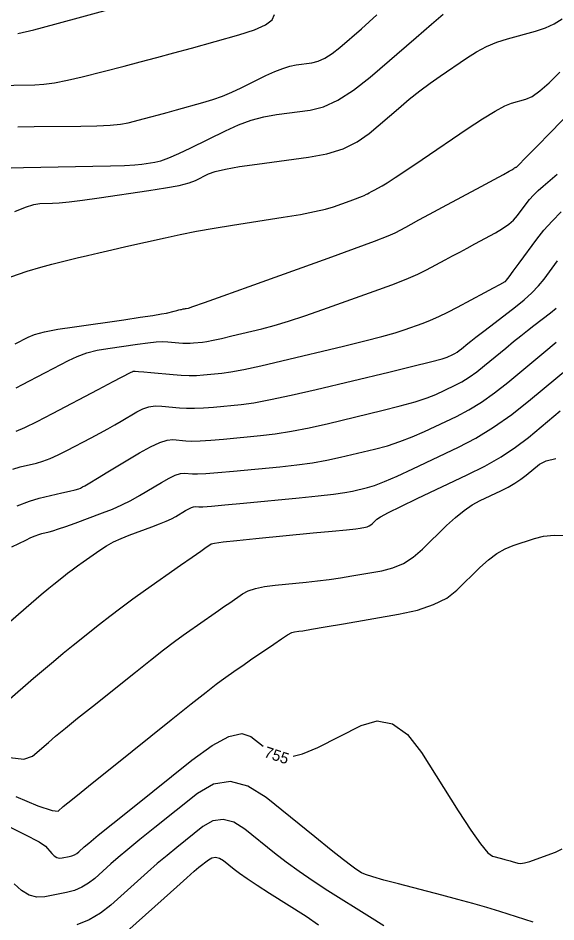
# Model space of a CAD drawing. Extents: x 2082232 to 2083549, y 592624 to 593832.
# Drawn here: x 2082518.1 to 2082552.2, y 592892.1 to 592949.4 of the extents above; entities that cross this region are included whole.
import ezdxf

# ---------------------------------------------------------------- set-up
doc = ezdxf.new("R2010")
doc.units = 0
doc.layers.add('DT_X_Contour_Major', color=7, linetype='Continuous')
doc.layers.add('DT_X_Contour_Minor', color=7, linetype='Continuous')

msp = doc.modelspace()

# ---------------------------------------------------------------- linework, layer by layer
at = {"layer": 'DT_X_Contour_Major'}
for points in [[(2082515.408, 592944.858), (2082515.81, 592944.932), (2082516.581, 592945.049), (2082517.244, 592945.12), (2082517.801, 592945.146), (2082519.143, 592945.157), (2082519.708, 592945.192), (2082520.398, 592945.29), (2082521.212, 592945.45), (2082522.149, 592945.673), (2082524.816, 592946.35), (2082525.832, 592946.611), (2082526.881, 592946.888), (2082527.963, 592947.179), (2082529.077, 592947.485), (2082532.093, 592948.32), (2082533.082, 592948.637), (2082533.788, 592948.96), (2082534.209, 592949.29), (2082534.347, 592949.627)], [(2082517.894, 592928.73), (2082518.717, 592929.161), (2082519.132, 592929.323), (2082519.763, 592929.486), (2082520.609, 592929.651), (2082521.669, 592929.817), (2082524.782, 592930.262), (2082525.827, 592930.414), (2082526.627, 592930.535), (2082527.182, 592930.626), (2082527.492, 592930.686), (2082527.991, 592930.807), (2082528.16, 592930.847), (2082528.292, 592930.879), (2082528.388, 592930.902), (2082528.448, 592930.916), (2082528.558, 592930.941), (2082528.601, 592930.95), (2082528.646, 592930.959), (2082528.695, 592930.968), (2082528.747, 592930.976), (2082528.888, 592930.998), (2082529.17, 592931.09), (2082529.908, 592931.348), (2082531.102, 592931.772), (2082532.752, 592932.364), (2082537.762, 592934.162), (2082539.437, 592934.769), (2082540.705, 592935.241), (2082541.566, 592935.578), (2082542.019, 592935.779), (2082542.685, 592936.136), (2082543.019, 592936.315), (2082543.52, 592936.585), (2082544.188, 592936.945), (2082545.024, 592937.395), (2082547.477, 592938.716), (2082548.287, 592939.154), (2082548.88, 592939.476), (2082549.254, 592939.682), (2082549.41, 592939.772), (2082549.537, 592939.857), (2082549.58, 592939.886), (2082549.615, 592939.907), (2082549.642, 592939.922), (2082549.661, 592939.93), (2082549.701, 592939.941), (2082549.85, 592940.084), (2082550.266, 592940.505), (2082550.95, 592941.205), (2082551.902, 592942.183), (2082554.795, 592945.162)], [(2082517.681, 592915.85), (2082518.576, 592916.289), (2082518.892, 592916.439), (2082519.166, 592916.557), (2082519.401, 592916.644), (2082519.594, 592916.7), (2082520.057, 592916.809), (2082520.29, 592916.875), (2082520.642, 592916.99), (2082521.113, 592917.154), (2082521.704, 592917.367), (2082523.439, 592918.002), (2082524.073, 592918.25), (2082524.675, 592918.516), (2082525.246, 592918.802), (2082525.784, 592919.107), (2082527.176, 592919.944), (2082527.658, 592920.216), (2082528.059, 592920.406), (2082528.378, 592920.512), (2082528.617, 592920.534), (2082529.145, 592920.484), (2082529.456, 592920.481), (2082529.994, 592920.508), (2082530.759, 592920.567), (2082531.75, 592920.656), (2082534.695, 592920.936), (2082535.763, 592921.052), (2082536.759, 592921.191), (2082537.682, 592921.352), (2082538.533, 592921.535), (2082540.705, 592922.054), (2082541.513, 592922.269), (2082542.309, 592922.526), (2082543.093, 592922.825), (2082543.864, 592923.166), (2082545.904, 592924.131), (2082546.681, 592924.537), (2082547.482, 592925.031), (2082548.307, 592925.613), (2082549.155, 592926.283), (2082551.45, 592928.189), (2082552.227, 592928.832)], [(2082535.532, 592902.581), (2082536.131, 592902.718), (2082537.095, 592903.13), (2082539.858, 592904.529), (2082540.874, 592904.815), (2082541.85, 592904.623), (2082542.786, 592903.954), (2082543.681, 592902.808), (2082546.014, 592899.114), (2082546.807, 592897.896), (2082547.433, 592897.009), (2082547.895, 592896.456), (2082548.19, 592896.234), (2082548.758, 592896.087), (2082548.961, 592896.034), (2082549.142, 592895.984), (2082549.303, 592895.938), (2082549.443, 592895.896), (2082549.787, 592895.788), (2082549.958, 592895.773), (2082550.21, 592895.812), (2082550.546, 592895.903), (2082550.963, 592896.047), (2082552.187, 592896.5), (2082552.613, 592896.694)], [(2082517.119, 592898.3), (2082518.513, 592897.617), (2082519.41, 592897.139), (2082519.811, 592896.864), (2082520.217, 592896.403), (2082520.372, 592896.257), (2082520.532, 592896.162), (2082520.697, 592896.118), (2082520.868, 592896.127), (2082521.331, 592896.218), (2082521.498, 592896.262), (2082521.654, 592896.327), (2082521.799, 592896.412), (2082521.932, 592896.517), (2082522.272, 592896.824), (2082522.56, 592897.066), (2082523.168, 592897.561), (2082524.097, 592898.309), (2082525.347, 592899.311), (2082529.107, 592902.32), (2082530.399, 592903.261), (2082531.454, 592903.825), (2082532.273, 592904.015), (2082532.856, 592903.828), (2082533.631, 592903.203)]]:
    msp.add_lwpolyline(points, dxfattribs=at)
at = {"layer": 'DT_X_Contour_Minor'}
for points in [[(2082518.07, 592948.404), (2082519.087, 592948.655), (2082520.403, 592949.003), (2082524.309, 592950.056)], [(2082517.636, 592939.887), (2082518.427, 592939.91), (2082519.516, 592939.933), (2082522.817, 592939.993), (2082523.94, 592940.019), (2082524.832, 592940.05), (2082525.493, 592940.087), (2082525.924, 592940.129), (2082526.765, 592940.25), (2082527.144, 592940.34), (2082527.65, 592940.522), (2082528.283, 592940.794), (2082529.043, 592941.158), (2082531.24, 592942.249), (2082532.061, 592942.62), (2082532.876, 592942.915), (2082533.685, 592943.134), (2082534.487, 592943.276), (2082536.62, 592943.556), (2082537.457, 592943.766), (2082538.369, 592944.184), (2082539.356, 592944.812), (2082540.418, 592945.648), (2082543.35, 592948.158), (2082544.325, 592948.998), (2082545.053, 592949.636)], [(2082518.065, 592942.501), (2082519.095, 592942.52), (2082522.061, 592942.543), (2082523.083, 592942.563), (2082523.924, 592942.605), (2082524.583, 592942.67), (2082525.062, 592942.757), (2082526.096, 592943.02), (2082526.515, 592943.128), (2082526.993, 592943.255), (2082527.533, 592943.401), (2082528.132, 592943.566), (2082529.812, 592944.032), (2082530.437, 592944.221), (2082531.051, 592944.439), (2082531.653, 592944.687), (2082532.246, 592944.964), (2082533.81, 592945.741), (2082534.37, 592946.002), (2082534.877, 592946.202), (2082535.33, 592946.342), (2082535.73, 592946.421), (2082536.726, 592946.552), (2082537.116, 592946.649), (2082537.542, 592946.845), (2082538.002, 592947.137), (2082538.498, 592947.528), (2082539.866, 592948.699), (2082540.367, 592949.146), (2082540.844, 592949.607)], [(2082517.878, 592937.126), (2082518.558, 592937.405), (2082519.086, 592937.575), (2082519.464, 592937.635), (2082520.272, 592937.65), (2082520.684, 592937.676), (2082521.315, 592937.743), (2082522.164, 592937.85), (2082523.232, 592937.998), (2082526.372, 592938.448), (2082527.441, 592938.615), (2082528.293, 592938.778), (2082528.928, 592938.937), (2082529.347, 592939.093), (2082530.173, 592939.503), (2082530.597, 592939.657), (2082531.25, 592939.814), (2082532.133, 592939.972), (2082533.245, 592940.132), (2082536.514, 592940.561), (2082537.674, 592940.776), (2082538.702, 592941.1), (2082539.597, 592941.533), (2082540.36, 592942.075), (2082542.218, 592943.666), (2082542.906, 592944.241), (2082543.576, 592944.773), (2082544.23, 592945.264), (2082544.867, 592945.711), (2082546.541, 592946.848), (2082547.174, 592947.244), (2082547.816, 592947.579), (2082548.469, 592947.853), (2082549.131, 592948.066), (2082550.91, 592948.552), (2082551.543, 592948.763), (2082552.107, 592949.028), (2082552.603, 592949.35)], [(2082517.614, 592932.974), (2082518.657, 592933.331), (2082519.526, 592933.603), (2082520.219, 592933.791), (2082521.834, 592934.181), (2082522.481, 592934.335), (2082523.21, 592934.506), (2082524.021, 592934.694), (2082524.915, 592934.898), (2082527.407, 592935.464), (2082528.376, 592935.674), (2082529.411, 592935.876), (2082530.514, 592936.073), (2082531.685, 592936.263), (2082534.896, 592936.762), (2082535.999, 592936.944), (2082536.899, 592937.114), (2082537.598, 592937.273), (2082538.094, 592937.42), (2082539.147, 592937.798), (2082539.499, 592937.926), (2082539.765, 592938.025), (2082539.946, 592938.096), (2082540.042, 592938.138), (2082540.182, 592938.213), (2082540.252, 592938.251), (2082540.357, 592938.308), (2082540.498, 592938.383), (2082540.673, 592938.478), (2082541.189, 592938.756), (2082541.492, 592938.938), (2082542.014, 592939.276), (2082542.756, 592939.769), (2082543.717, 592940.418), (2082546.572, 592942.357), (2082547.552, 592943.005), (2082548.349, 592943.494), (2082548.964, 592943.825), (2082549.396, 592943.998), (2082550.306, 592944.246), (2082550.696, 592944.423), (2082551.187, 592944.767), (2082551.777, 592945.278), (2082552.466, 592945.955)], [(2082517.956, 592925.933), (2082518.359, 592926.145), (2082518.803, 592926.377), (2082519.288, 592926.632), (2082519.814, 592926.907), (2082521.27, 592927.67), (2082521.836, 592927.933), (2082522.443, 592928.15), (2082523.089, 592928.32), (2082523.775, 592928.444), (2082525.659, 592928.713), (2082526.31, 592928.798), (2082526.848, 592928.852), (2082527.274, 592928.875), (2082527.588, 592928.866), (2082528.275, 592928.8), (2082528.527, 592928.782), (2082528.768, 592928.774), (2082528.997, 592928.777), (2082529.215, 592928.792), (2082529.783, 592928.846), (2082530.058, 592928.885), (2082530.46, 592928.962), (2082530.988, 592929.076), (2082531.643, 592929.229), (2082533.556, 592929.686), (2082534.336, 592929.89), (2082535.24, 592930.161), (2082536.27, 592930.499), (2082537.424, 592930.902), (2082540.669, 592932.067), (2082541.79, 592932.48), (2082542.718, 592932.842), (2082543.453, 592933.156), (2082543.997, 592933.42), (2082545.189, 592934.059), (2082545.641, 592934.302), (2082546.105, 592934.551), (2082546.579, 592934.806), (2082547.065, 592935.067), (2082548.376, 592935.773), (2082548.831, 592936.04), (2082549.215, 592936.31), (2082549.528, 592936.584), (2082549.77, 592936.862), (2082550.319, 592937.607), (2082550.54, 592937.887), (2082550.794, 592938.169), (2082551.078, 592938.452), (2082551.395, 592938.736), (2082552.281, 592939.497)], [(2082517.964, 592923.183), (2082518.518, 592923.431), (2082519.286, 592923.808), (2082520.266, 592924.314), (2082523.165, 592925.833), (2082524.117, 592926.332), (2082525.211, 592926.906), (2082525.354, 592926.981), (2082525.375, 592926.992), (2082525.383, 592926.996), (2082525.392, 592926.999), (2082525.402, 592927.002), (2082525.411, 592927.004), (2082525.439, 592927.007), (2082525.514, 592927.002), (2082525.718, 592926.984), (2082526.052, 592926.954), (2082526.515, 592926.91), (2082527.922, 592926.776), (2082528.439, 592926.737), (2082528.932, 592926.721), (2082529.402, 592926.728), (2082529.849, 592926.758), (2082531.011, 592926.868), (2082531.576, 592926.948), (2082532.399, 592927.106), (2082533.481, 592927.341), (2082534.821, 592927.653), (2082538.74, 592928.589), (2082540.082, 592928.917), (2082541.17, 592929.197), (2082542.003, 592929.43), (2082542.581, 592929.615), (2082543.784, 592930.047), (2082544.259, 592930.232), (2082544.782, 592930.462), (2082545.354, 592930.739), (2082545.974, 592931.061), (2082547.692, 592931.982), (2082548.257, 592932.284), (2082548.662, 592932.501), (2082548.995, 592932.68), (2082549.014, 592932.69), (2082549.073, 592932.765), (2082549.235, 592932.982), (2082549.501, 592933.341), (2082549.871, 592933.842), (2082550.995, 592935.368), (2082551.449, 592935.942), (2082551.968, 592936.519), (2082552.552, 592937.099)], [(2082517.742, 592920.783), (2082518.207, 592920.925), (2082519.24, 592921.169), (2082519.651, 592921.286), (2082520.11, 592921.457), (2082520.617, 592921.681), (2082521.171, 592921.958), (2082522.714, 592922.766), (2082523.266, 592923.059), (2082523.767, 592923.333), (2082524.217, 592923.587), (2082524.616, 592923.821), (2082525.609, 592924.418), (2082525.988, 592924.609), (2082526.379, 592924.734), (2082526.782, 592924.793), (2082527.198, 592924.786), (2082528.322, 592924.679), (2082528.774, 592924.652), (2082529.284, 592924.65), (2082529.854, 592924.674), (2082530.483, 592924.724), (2082532.239, 592924.891), (2082533.031, 592924.997), (2082534.089, 592925.191), (2082535.415, 592925.472), (2082537.007, 592925.84), (2082541.607, 592926.939), (2082543.133, 592927.307), (2082544.26, 592927.588), (2082544.989, 592927.781), (2082545.319, 592927.887), (2082545.667, 592928.051), (2082545.799, 592928.12), (2082545.936, 592928.205), (2082546.076, 592928.304), (2082546.221, 592928.418), (2082546.612, 592928.743), (2082546.814, 592928.906), (2082547.126, 592929.15), (2082547.548, 592929.475), (2082548.079, 592929.882), (2082549.644, 592931.075), (2082550.198, 592931.521), (2082550.684, 592931.964), (2082551.104, 592932.402), (2082551.456, 592932.838), (2082552.308, 592933.993)], [(2082518.033, 592918.461), (2082518.803, 592918.753), (2082519.419, 592918.935), (2082520.858, 592919.274), (2082521.337, 592919.389), (2082521.693, 592919.478), (2082521.928, 592919.543), (2082522.041, 592919.582), (2082522.178, 592919.655), (2082522.317, 592919.735), (2082522.631, 592919.921), (2082523.12, 592920.213), (2082523.783, 592920.612), (2082525.786, 592921.816), (2082526.482, 592922.208), (2082527.067, 592922.479), (2082527.542, 592922.63), (2082527.907, 592922.66), (2082528.734, 592922.582), (2082529.115, 592922.566), (2082529.639, 592922.579), (2082530.306, 592922.62), (2082531.116, 592922.69), (2082533.467, 592922.913), (2082534.397, 592923.025), (2082535.424, 592923.191), (2082536.548, 592923.412), (2082537.77, 592923.688), (2082541.156, 592924.496), (2082542.323, 592924.788), (2082543.285, 592925.057), (2082544.041, 592925.303), (2082544.591, 592925.526), (2082545.785, 592926.091), (2082546.24, 592926.329), (2082546.709, 592926.618), (2082547.192, 592926.958), (2082547.688, 592927.351), (2082549.031, 592928.466), (2082549.52, 592928.869), (2082549.981, 592929.242), (2082550.414, 592929.585), (2082550.818, 592929.897), (2082551.859, 592930.691), (2082552.227, 592930.988)], [(2082515.759, 592909.554), (2082518.113, 592911.589), (2082518.915, 592912.28), (2082519.554, 592912.827), (2082520.031, 592913.23), (2082520.344, 592913.488), (2082520.964, 592913.984), (2082521.217, 592914.181), (2082521.51, 592914.401), (2082521.844, 592914.644), (2082522.218, 592914.91), (2082523.271, 592915.649), (2082523.684, 592915.916), (2082524.131, 592916.163), (2082524.615, 592916.39), (2082525.134, 592916.596), (2082526.564, 592917.12), (2082527.062, 592917.309), (2082527.483, 592917.483), (2082527.826, 592917.642), (2082528.092, 592917.786), (2082528.699, 592918.151), (2082528.908, 592918.27), (2082529.083, 592918.352), (2082529.222, 592918.398), (2082529.326, 592918.408), (2082529.556, 592918.386), (2082529.798, 592918.395), (2082530.349, 592918.437), (2082531.211, 592918.513), (2082532.384, 592918.622), (2082535.923, 592918.959), (2082537.13, 592919.08), (2082538.094, 592919.191), (2082538.816, 592919.292), (2082539.296, 592919.382), (2082540.254, 592919.611), (2082540.703, 592919.75), (2082541.333, 592919.995), (2082542.144, 592920.347), (2082543.137, 592920.806), (2082546.023, 592922.171), (2082547.121, 592922.744), (2082548.249, 592923.439), (2082549.408, 592924.256), (2082550.598, 592925.195), (2082553.81, 592927.863)], [(2082517.378, 592906.068), (2082519.059, 592907.521), (2082519.689, 592908.06), (2082520.318, 592908.589), (2082520.946, 592909.107), (2082521.573, 592909.613), (2082523.243, 592910.95), (2082523.896, 592911.462), (2082524.601, 592911.996), (2082525.358, 592912.55), (2082526.167, 592913.126), (2082528.394, 592914.689), (2082529.132, 592915.207), (2082529.675, 592915.588), (2082530.023, 592915.832), (2082530.177, 592915.939), (2082530.328, 592916.043), (2082530.547, 592916.093), (2082531.094, 592916.167), (2082531.968, 592916.264), (2082533.169, 592916.384), (2082536.807, 592916.736), (2082538.016, 592916.854), (2082538.916, 592916.944), (2082539.506, 592917.007), (2082539.786, 592917.043), (2082540.12, 592917.101), (2082540.242, 592917.132), (2082540.358, 592917.183), (2082540.467, 592917.252), (2082540.57, 592917.34), (2082540.837, 592917.601), (2082541.073, 592917.757), (2082541.58, 592918.029), (2082542.359, 592918.416), (2082543.409, 592918.918), (2082546.57, 592920.413), (2082547.703, 592920.982), (2082548.729, 592921.569), (2082549.648, 592922.174), (2082550.461, 592922.796), (2082552.487, 592924.479)], [(2082517.554, 592902.497), (2082518.448, 592902.397), (2082518.997, 592902.582), (2082520.005, 592903.452), (2082520.463, 592903.84), (2082521.081, 592904.35), (2082521.861, 592904.983), (2082522.801, 592905.739), (2082525.523, 592907.917), (2082526.478, 592908.676), (2082527.304, 592909.318), (2082527.999, 592909.844), (2082528.565, 592910.253), (2082529.899, 592911.19), (2082530.375, 592911.524), (2082530.802, 592911.821), (2082531.179, 592912.084), (2082531.508, 592912.31), (2082532.317, 592912.867), (2082532.675, 592913.059), (2082533.14, 592913.216), (2082533.713, 592913.339), (2082534.394, 592913.427), (2082536.353, 592913.616), (2082537.085, 592913.694), (2082537.813, 592913.785), (2082538.537, 592913.89), (2082539.256, 592914.007), (2082541.168, 592914.34), (2082541.867, 592914.519), (2082542.53, 592914.807), (2082543.157, 592915.204), (2082543.747, 592915.71), (2082545.274, 592917.205), (2082545.837, 592917.724), (2082546.379, 592918.161), (2082546.901, 592918.517), (2082547.402, 592918.79), (2082548.712, 592919.409), (2082549.182, 592919.645), (2082549.607, 592919.889), (2082549.988, 592920.139), (2082550.325, 592920.397), (2082551.164, 592921.094), (2082551.584, 592921.316), (2082552.213, 592921.458)], [(2082517.94, 592900.021), (2082519.344, 592899.435), (2082520.236, 592899.126), (2082520.617, 592899.095), (2082520.95, 592899.384), (2082521.236, 592899.62), (2082521.845, 592900.112), (2082522.776, 592900.86), (2082524.03, 592901.864), (2082527.802, 592904.884), (2082529.061, 592905.889), (2082530.007, 592906.64), (2082530.641, 592907.138), (2082530.963, 592907.381), (2082531.405, 592907.691), (2082531.619, 592907.84), (2082531.929, 592908.055), (2082532.335, 592908.335), (2082532.838, 592908.681), (2082534.307, 592909.692), (2082534.802, 592910.024), (2082535.186, 592910.265), (2082535.458, 592910.414), (2082535.619, 592910.47), (2082535.899, 592910.497), (2082536.154, 592910.534), (2082536.711, 592910.626), (2082537.568, 592910.772), (2082538.726, 592910.972), (2082542.216, 592911.579), (2082543.43, 592911.845), (2082544.453, 592912.188), (2082545.286, 592912.608), (2082545.929, 592913.106), (2082547.39, 592914.535), (2082547.932, 592915.025), (2082548.465, 592915.423), (2082548.988, 592915.729), (2082549.501, 592915.943), (2082550.856, 592916.39), (2082551.419, 592916.523), (2082552.091, 592916.588), (2082552.873, 592916.584)], [(2082550.772, 592892.056), (2082548.646, 592892.725), (2082547.819, 592892.978), (2082546.932, 592893.235), (2082545.987, 592893.496), (2082544.981, 592893.762), (2082542.222, 592894.475), (2082541.3, 592894.72), (2082540.602, 592894.92), (2082540.129, 592895.073), (2082539.881, 592895.182), (2082539.519, 592895.41), (2082539.255, 592895.603), (2082538.733, 592896.008), (2082537.954, 592896.627), (2082536.919, 592897.459), (2082533.814, 592899.963), (2082532.668, 592900.683), (2082531.56, 592900.965), (2082530.489, 592900.81), (2082529.456, 592900.217), (2082526.752, 592898.052), (2082525.817, 592897.299), (2082525.04, 592896.663), (2082524.423, 592896.144), (2082523.963, 592895.742), (2082522.951, 592894.827), (2082522.554, 592894.514), (2082522.122, 592894.262), (2082521.657, 592894.069), (2082521.157, 592893.937), (2082519.779, 592893.665), (2082519.27, 592893.64), (2082518.777, 592893.769), (2082518.3, 592894.052), (2082517.838, 592894.49)], [(2082541.283, 592891.829), (2082540.373, 592892.385), (2082537.747, 592894.043), (2082536.796, 592894.659), (2082535.914, 592895.262), (2082535.101, 592895.853), (2082534.357, 592896.432), (2082532.463, 592897.959), (2082531.764, 592898.398), (2082531.089, 592898.57), (2082530.436, 592898.475), (2082529.806, 592898.113), (2082528.156, 592896.793), (2082527.536, 592896.289), (2082526.912, 592895.765), (2082526.285, 592895.223), (2082525.655, 592894.661), (2082523.969, 592893.138), (2082523.308, 592892.617), (2082522.59, 592892.197), (2082521.816, 592891.876)], [(2082524.987, 592891.449), (2082527.346, 592893.58), (2082528.148, 592894.301), (2082528.784, 592894.867), (2082529.255, 592895.279), (2082529.561, 592895.535), (2082530.155, 592896.01), (2082530.382, 592896.14), (2082530.617, 592896.175), (2082530.861, 592896.113), (2082531.113, 592895.954), (2082531.795, 592895.404), (2082532.127, 592895.155), (2082532.612, 592894.821), (2082533.25, 592894.402), (2082534.041, 592893.897), (2082536.354, 592892.436), (2082537.138, 592891.887)]]:
    msp.add_lwpolyline(points, dxfattribs=at)

# ---------------------------------------------------------------- texts
at = {"layer": 'DT_X_Contour_Major'}
msp.add_text('755', height=0.7, rotation=341.88032, dxfattribs=at).set_placement((2082533.642, 592902.543))

doc.saveas('drawing.dxf')
